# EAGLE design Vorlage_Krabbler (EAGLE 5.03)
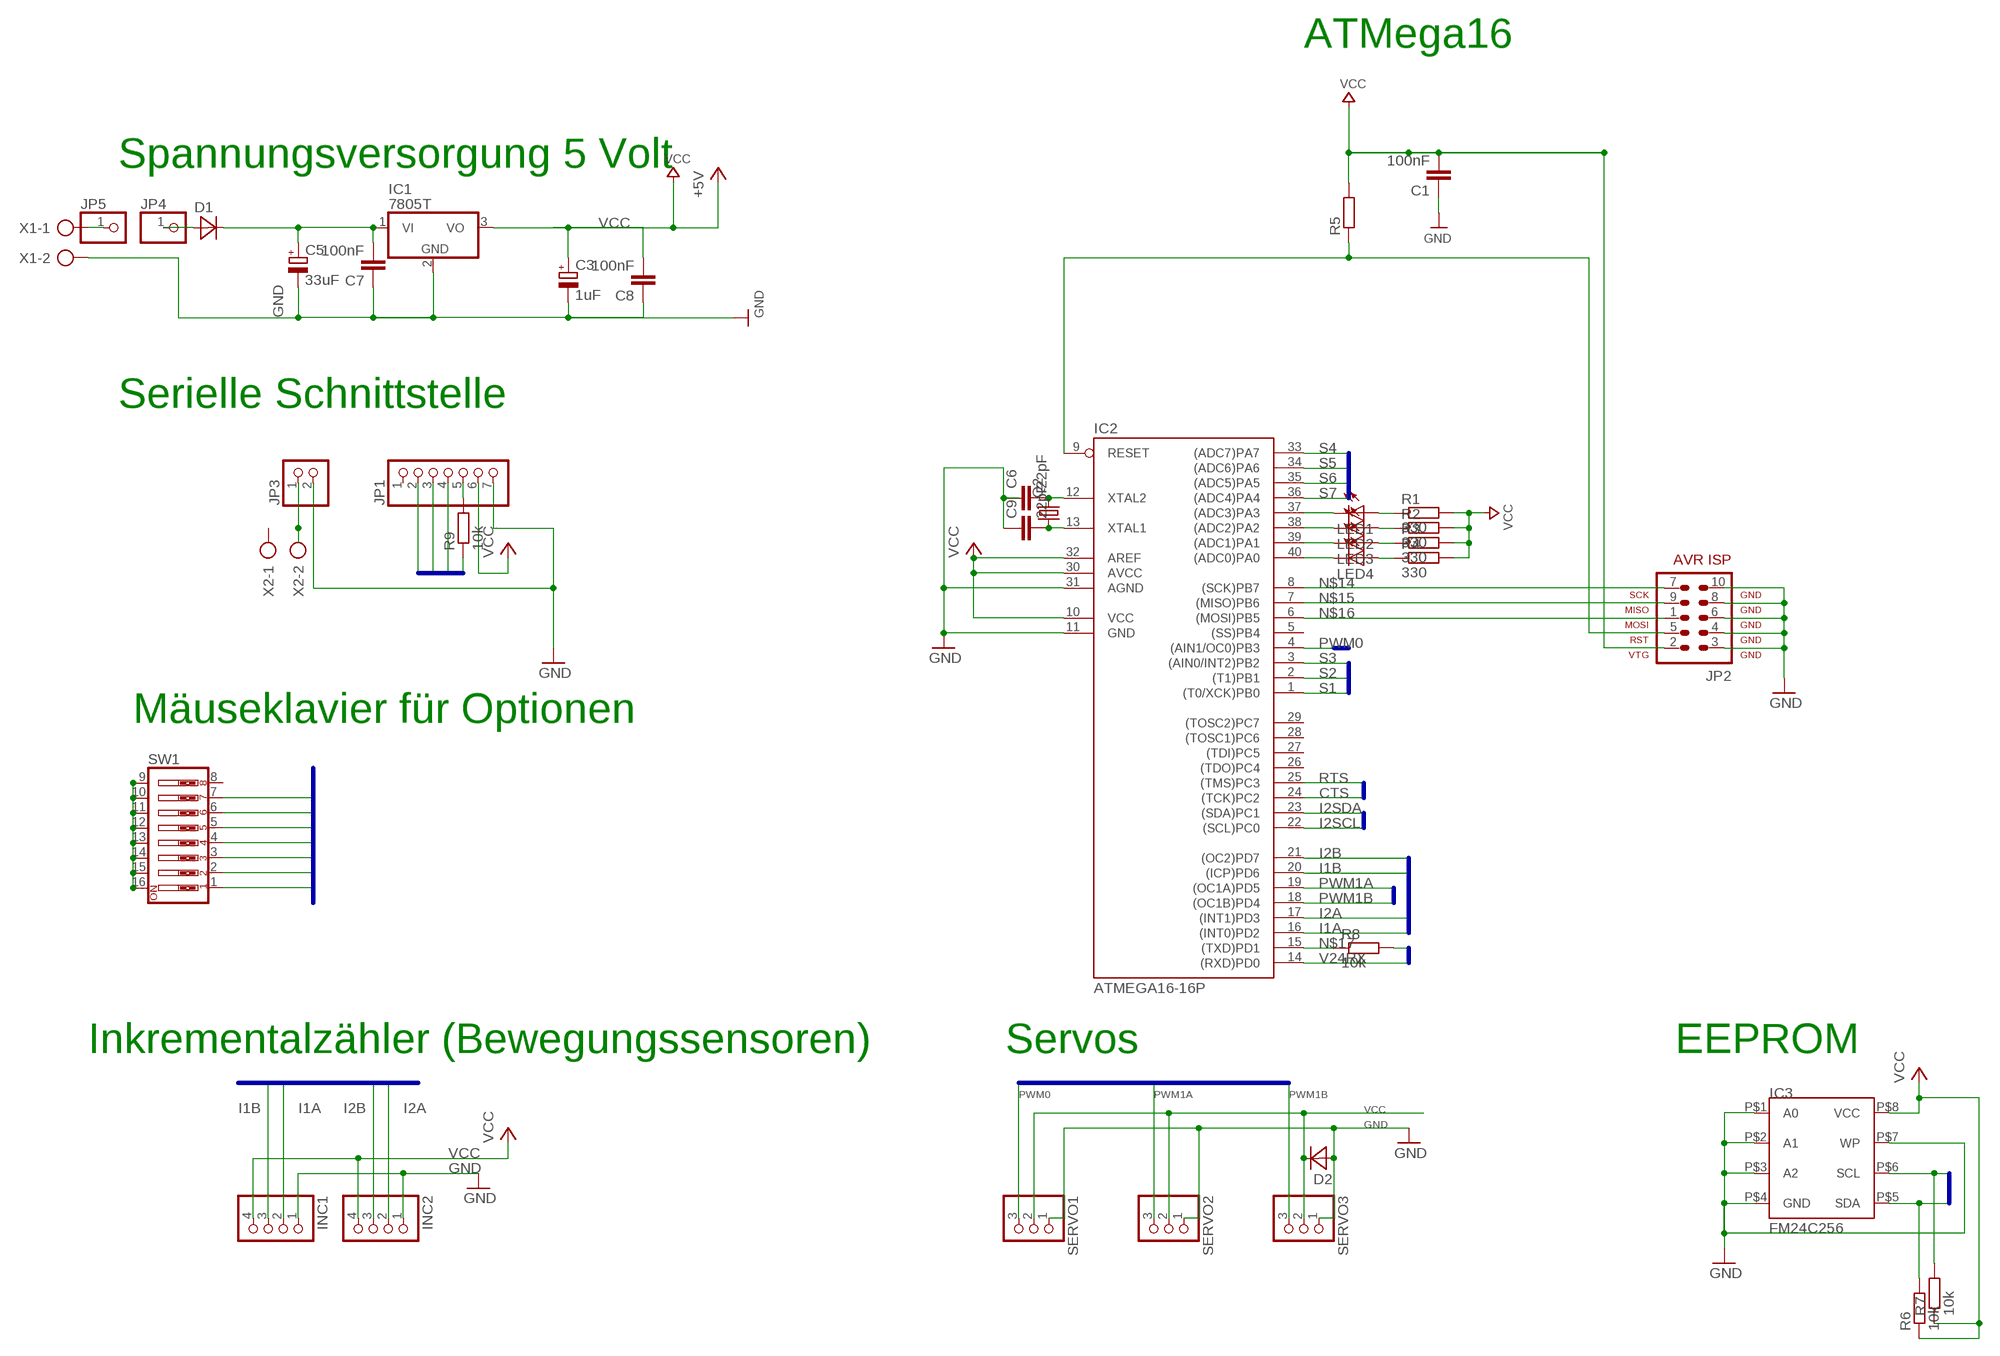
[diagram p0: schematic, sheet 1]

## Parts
C1  100nF  C-EUC0805  [C0805]
C3  1uF  CPOL-EUE2.5-5  [E2,5-5]
C5  33uF  CPOL-EUE2.5-5  [E2,5-5]
C6  22pF  C-EUC0805  [C0805]
C7  100nF  C-EUC0805  [C0805]
C8  100nF  C-EUC0805  [C0805]
C9  22pF  C-EUC0805  [C0805]
D1  DIODE-10  [D-10]
D2  DIODE-10  [D-10]
IC1  7805T  [TO220H]
IC2  ATMEGA16-16P  [DIL40]
IC3  FM24C256  [EIAJ-SOIC-8]
INC1  PINHD-1X4  [1X04]
INC2  PINHD-1X4  [1X04]
JP1  PINHD-1X7  [1X07]
JP2  AVR-ISP-10  [AVR-ISP-10]
JP3  PINHD-1X2  [1X02]
JP4  PINHD-1X1  [1X01]
JP5  PINHD-1X1  [1X01]
LED1  LED5MM  [LED5MM]
LED2  LED5MM  [LED5MM]
LED3  LED5MM  [LED5MM]
LED4  LED5MM  [LED5MM]
Q2  CRYTALHC49S  [HC49/S]
R1  330  R-EU_M1206  [M1206]
R2  330  R-EU_M1206  [M1206]
R3  330  R-EU_M1206  [M1206]
R4  330  R-EU_M1206  [M1206]
R5  R-EU_M1206  [M1206]
R6  10k  R-EU_M1206  [M1206]
R7  10k  R-EU_M1206  [M1206]
R8  10k  R-EU_M1206  [M1206]
R9  10k  R-EU_M1206  [M1206]
SERVO1  PINHD-1X3  [1X03]
SERVO2  PINHD-1X3  [1X03]
SERVO3  PINHD-1X3  [1X03]
SW1  SW_DIP-8  [EDG-08]
X1  AK500/2  [AK500/2]
X2  AK500/2  [AK500/2]

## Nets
/RESET: IC2.9(RESET) JP2.5 R5.1
CTS: IC2.24((TCK)PC2) JP1.2
GND: C1.1 C3.- C5.- C6.1 C7.1 C8.1 C9.1 D2.1(A) IC1.2(GND) IC2.11(GND) IC2.31(AGND) IC3.P$1(A0) IC3.P$2(A1) IC3.P$3(A2) IC3.P$4(GND) IC3.P$7(WP) INC1.1 INC2.1 JP1.7 JP2.3 JP2.4 JP2.6 JP2.8 JP2.10 JP3.2 SERVO1.1 SERVO2.1 SERVO3.1 SW1.9 SW1.10 SW1.11 SW1.12 SW1.13 SW1.14 SW1.15 SW1.16 X1.2
I1A: IC2.16((INT0)PD2) INC1.2
I1B: IC2.20((ICP)PD6) INC1.3
I2A: IC2.17((INT1)PD3) INC2.2
I2B: IC2.21((OC2)PD7) INC2.3
I2SCL: IC2.22((SCL)PC0) IC3.P$6(SCL) R7.2
I2SDA: IC2.23((SDA)PC1) IC3.P$5(SDA) R6.2
N$1: LED1.A R1.1
N$2: LED2.A R2.1
N$3: C6.2 IC2.12(XTAL2) Q2.2
N$4: C9.2 IC2.13(XTAL1) Q2.1
N$5: IC2.37((ADC3)PA3) LED1.K(C)
N$6: LED3.A R3.1
N$7: LED4.A R4.1
N$8: IC2.38((ADC2)PA2) LED2.K(C)
N$9: D1.1(A) JP4.1
N$10: IC2.39((ADC1)PA1) LED3.K(C)
N$11: IC2.40((ADC0)PA0) LED4.K(C)
N$12: C5.+ C7.2 D1.2(K) IC1.1(VI)
N$13: JP5.1 X1.1
N$14: IC2.8((SCK)PB7) JP2.7
N$15: IC2.7((MISO)PB6) JP2.9
N$16: IC2.6((MOSI)PB5) JP2.1
N$17: IC2.15((TXD)PD1) R8.1
N$18: JP3.1 X2.2
N$19: JP1.5 R9.2
PWM0: IC2.4((AIN1/OC0)PB3) SERVO1.3
PWM1A: IC2.19((OC1A)PD5) SERVO2.3
PWM1B: IC2.18((OC1B)PD4) SERVO3.3
RTS: IC2.25((TMS)PC3) R9.1
S1: IC2.1((T0/XCK)PB0) SW1.1
S2: IC2.2((T1)PB1) SW1.2
S3: IC2.3((AIN0/INT2)PB2) SW1.3
S4: IC2.33((ADC7)PA7) SW1.4
S5: IC2.34((ADC6)PA6) SW1.5
S6: IC2.35((ADC5)PA5) SW1.6
S7: IC2.36((ADC4)PA4) SW1.7
V24RX: IC2.14((RXD)PD0) JP1.3
V24TX: JP1.4 R8.2
VCC: C1.2 C3.+ C8.2 D2.2(K) IC1.3(VO) IC2.10(VCC) IC2.30(AVCC) IC2.32(AREF) IC3.P$8(VCC) INC1.4 INC2.4 JP1.6 JP2.2 R1.2 R2.2 R3.2 R4.2 R5.2 R6.1 R7.1 SERVO1.2 SERVO2.2 SERVO3.2 ; supply symbol labelled +5V
Unconnected: IC2.5((SS)PB4) IC2.26((TDO)PC4) IC2.27((TDI)PC5) IC2.28((TOSC1)PC6) IC2.29((TOSC2)PC7) JP1.1 SW1.8 X2.1

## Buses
PWM0,PWM1A,PWM1B
V24RX,V24TX,RTS,CTS
I1A,I1B,I2A,I2B
I2SCL,I2SDA
S1,S2,S3,S4,S5,S6,S7

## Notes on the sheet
- ATMega16
- Spannungsversorgung 5 Volt
- Serielle Schnittstelle
- Mäuseklavier für Optionen
- Servos | EEPROM
- Inkrementalzähler (Bewegungssensoren)

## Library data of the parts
C1 C6-C9 = rcl:C-EU: CAPACITOR, European symbol
C3 C5 = rcl:CPOL-EU: POLARIZED CAPACITOR, European symbol
D1 D2 = discrete:DIODE-10
IC1 = linear:78*: Positive VOLTAGE REGULATOR
IC2 = avr:ATMEGA16*P: MICROCONTROLLER 16 Kbytes FLASH 1 kbytes SRAM 512 bytes EEPROM USART 8-channel 10 bit ADC
IC3 = ramtron:FM24C256
INC1 INC2 = pinhead:PINHD-1X4: PIN HEADER
JP1 = pinhead:PINHD-1X7: PIN HEADER
JP2 = atmel_3:AVR-ISP-10: AVR ISP-10 Serial Programming Header
JP3 = pinhead:PINHD-1X2: PIN HEADER
JP4 JP5 = pinhead:PINHD-1X1: PIN HEADER
LED1-LED4 = LED:LED: LED
Q2 = crystal:CRYTAL: CRYSTAL
R1-R9 = rcl:R-EU_: RESISTOR, European symbol
SERVO1-SERVO3 = pinhead:PINHD-1X3: PIN HEADER
SW1 = special:SW_DIP-8: DIP SWITCH
X1 X2 = con-ptr500:AK500/2: CONNECTOR

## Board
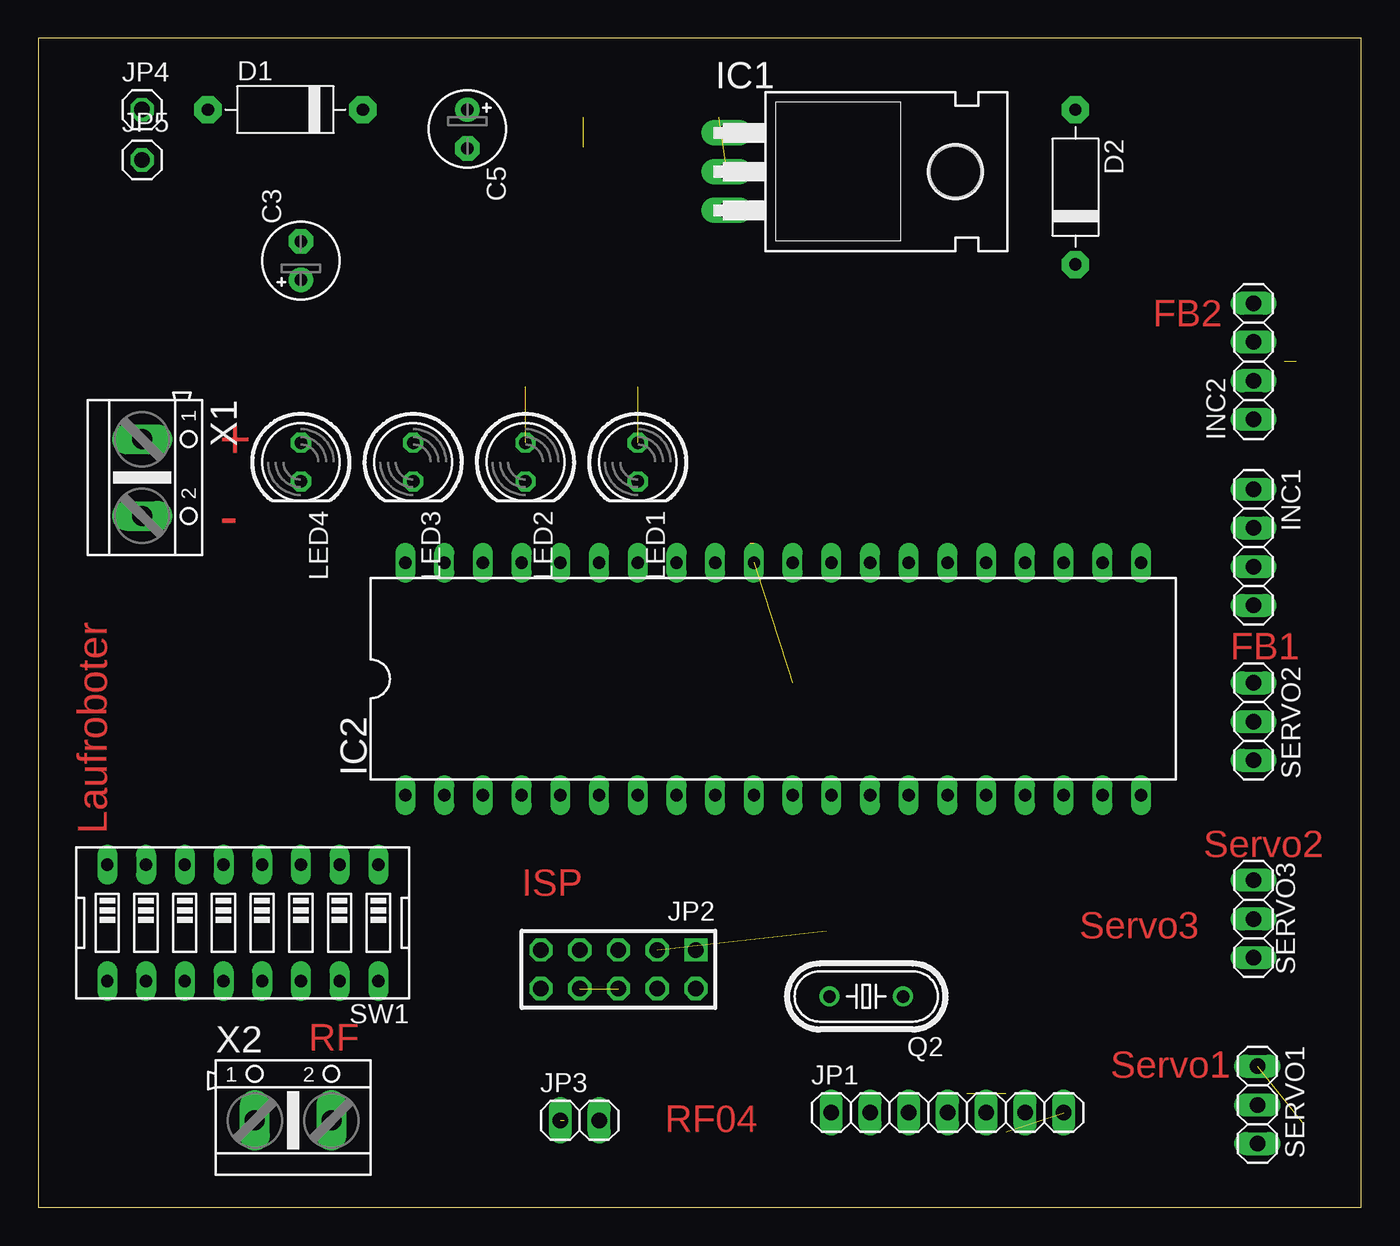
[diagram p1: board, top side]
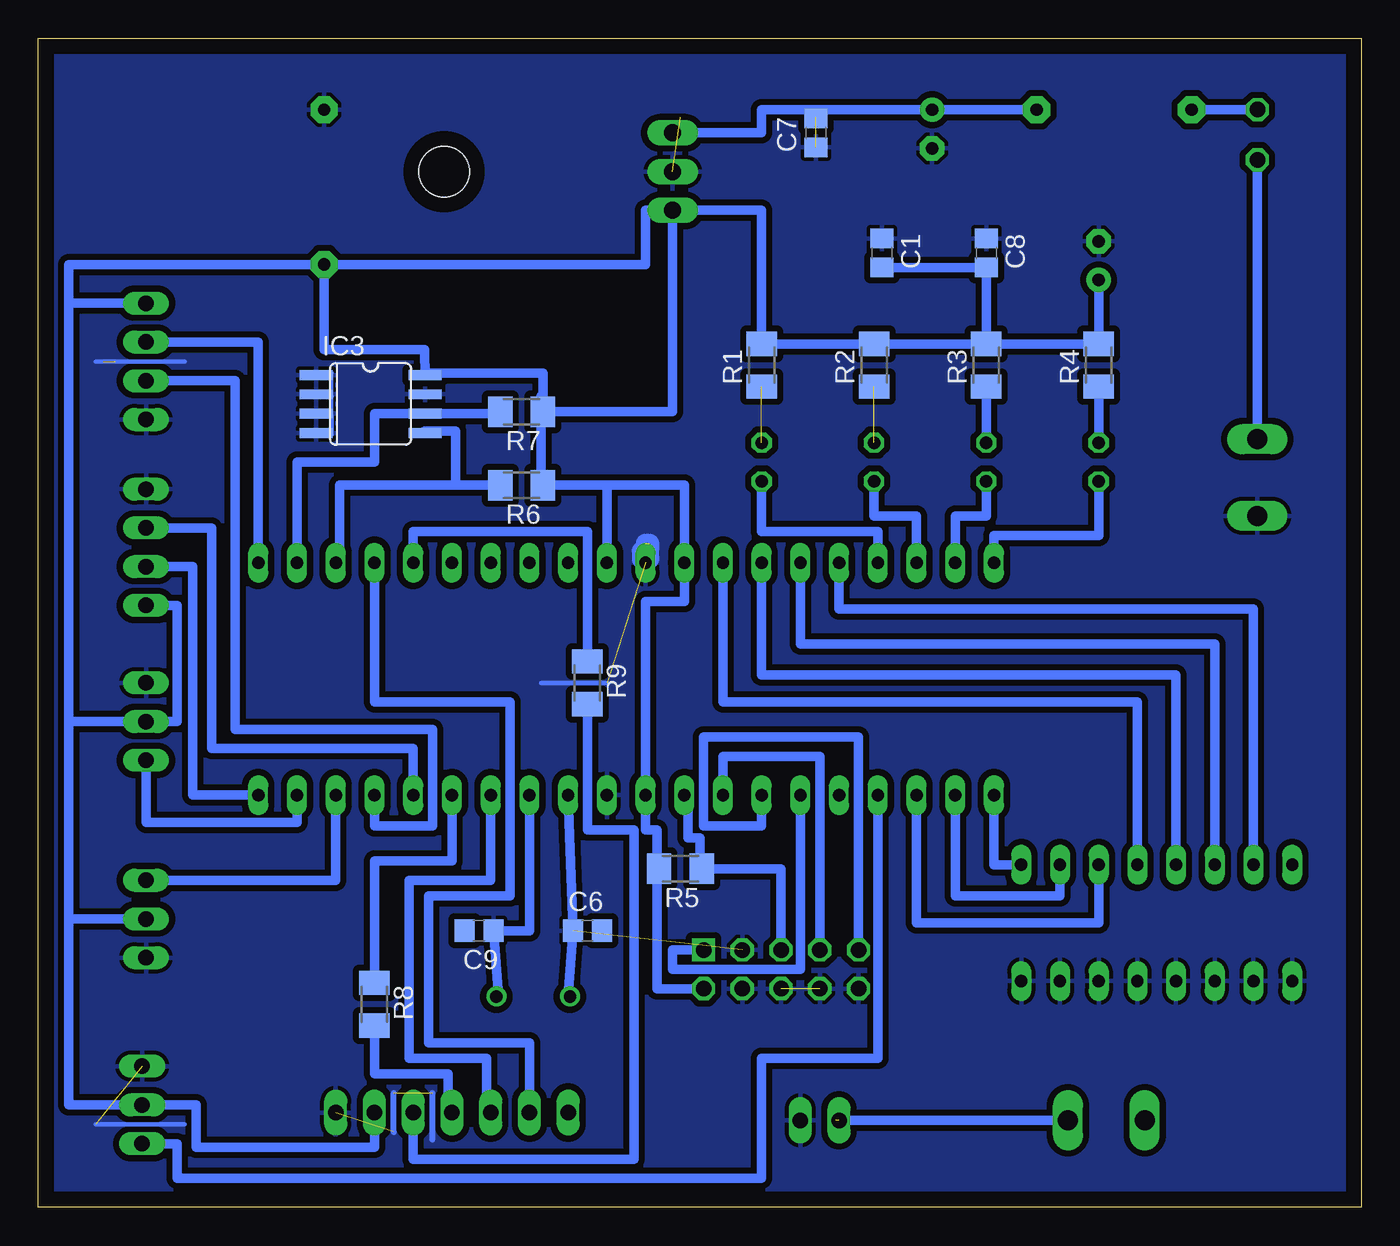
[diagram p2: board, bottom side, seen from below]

Size 86.79 x 76.7 mm. Coordinates in mm from the lower left corner, seen from the top.
Outline: 0,0 86.79,0 86.79,76.7 0,76.7 0,0
Copper layers (1*16): Top 0.035mm / dielectric 1.5mm / Bottom 0.035mm
Design rules "default": minimum track width 10mil, minimum drill 24mil, track to track 16mil, track to pad 16mil, pad to pad 16mil, via to via 16mil, smd to smd 16mil, copper to edge 40mil, drill to drill 16mil, minimum pad ring 10mil, minimum via ring 8mil, stop-mask expansion 4mil, vias tented up to drill 0mil, thermal gap 10mil

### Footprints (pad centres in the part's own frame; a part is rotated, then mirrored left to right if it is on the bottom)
C0805 = smd 1.3 x 1.5: 1 -0.95,0; 2 0.95,0
E2,5-5 = drill 0.813 pad 1.6 round: + -1.27,0 | drill 0.813 pad 1.6 octagon: - 1.27,0
D-10 = drill 0.813 pad 1.778 octagon: 1 -5.08,0; 2 5.08,0
TO220H = drill 1.118 long: 1 -2.54,-10.16; 2 0,-10.16; 3 2.54,-10.16 | hole 3.302: 0,4.826
DIL40 = drill 0.813 long: 1 -24.13,-7.62; 2 -21.59,-7.62; 3 -19.05,-7.62; 4 -16.51,-7.62; 5 -13.97,-7.62; 6 -11.43,-7.62; 7 -8.89,-7.62; 8 -6.35,-7.62; 9 -3.81,-7.62; 10 -1.27,-7.62; 11 1.27,-7.62; 12 3.81,-7.62; 13 6.35,-7.62; 14 8.89,-7.62; 15 11.43,-7.62; 16 13.97,-7.62; 17 16.51,-7.62; 18 19.05,-7.62; 19 21.59,-7.62; 20 24.13,-7.62; 21 24.13,7.62; 22 21.59,7.62; 23 19.05,7.62; 24 16.51,7.62; 25 13.97,7.62; 26 11.43,7.62; 27 8.89,7.62; 28 6.35,7.62; 29 3.81,7.62; 30 1.27,7.62; 31 -1.27,7.62; 32 -3.81,7.62; 33 -6.35,7.62; 34 -8.89,7.62; 35 -11.43,7.62; 36 -13.97,7.62; 37 -16.51,7.62; 38 -19.05,7.62; 39 -21.59,7.62; 40 -24.13,7.62
EIAJ-SOIC-8 = smd 0.65 x 2.15: P$1 -1.905,-3.576; P$2 -0.635,-3.576; P$3 0.635,-3.576; P$4 1.905,-3.576; P$5 1.905,3.576; P$6 0.635,3.576; P$7 -0.635,3.576; P$8 -1.905,3.576
1X04 = drill 1.016 long: 1 -3.81,0; 2 -1.27,0; 3 1.27,0; 4 3.81,0
1X07 = drill 1.016 long: 1 -7.62,0; 2 -5.08,0; 3 -2.54,0; 4 0,0; 5 2.54,0; 6 5.08,0; 7 7.62,0
AVR-ISP-10 = drill 1.016 square: 1 -5.08,-1.27 | drill 1.016 octagon: 2 -5.08,1.27; 3 -2.54,-1.27; 4 -2.54,1.27; 5 0,-1.27; 6 0,1.27; 7 2.54,-1.27; 8 2.54,1.27; 9 5.08,-1.27; 10 5.08,1.27
1X02 = drill 1.016 long: 1 -1.27,0; 2 1.27,0
1X01 = drill 1.016 octagon: 1 0,0
LED5MM = drill 0.813 octagon: A -1.27,0; K 1.27,0
HC49/S = drill 0.813 round: 1 -2.413,0; 2 2.413,0
M1206 = smd 1.6 x 2: 1 -1.4,0; 2 1.4,0
1X03 = drill 1.016 long: 1 -2.54,0; 2 0,0; 3 2.54,0
EDG-08 = drill 0.813 long: 1 -8.89,-3.81; 2 -6.35,-3.81; 3 -3.81,-3.81; 4 -1.27,-3.81; 5 1.27,-3.81; 6 3.81,-3.81; 7 6.35,-3.81; 8 8.89,-3.81; 9 8.89,3.81; 10 6.35,3.81; 11 3.81,3.81; 12 1.27,3.81; 13 -1.27,3.81; 14 -3.81,3.81; 15 -6.35,3.81; 16 -8.89,3.81
AK500/2 = drill 1.321 long: 1 -2.515,0; 2 2.515,0

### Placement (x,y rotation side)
C1  31.46,62.61 270 bottom
C3  17.23,62.1 90 top
C5  28.16,70.73 270 top
C6  50.76,18.16 0 bottom
C7  35.78,70.48 90 bottom
C8  24.6,62.61 270 bottom
C9  57.87,18.16 180 bottom
D1  16.22,72 0 top
D2  68.03,66.92 270 top
IC1  55.33,67.94 270 top
IC2  48.22,34.67 0 top
IC3  64.99,52.7 270 bottom
INC1  79.72,43.3 270 top
INC2  79.72,55.49 90 top
JP1  59.65,6.22 0 top
JP2  38.06,15.62 180 top
JP3  35.52,5.71 0 top
JP4  6.82,72 0 top
JP5  6.82,68.7 0 top
LED1  39.33,48.89 270 top
LED2  31.97,48.89 270 top
LED3  24.6,48.89 270 top
LED4  17.23,48.89 270 top
Q2  54.32,13.84 180 top
R1  39.33,55.24 90 bottom
R2  31.97,55.24 90 bottom
R3  24.6,55.24 90 bottom
R4  17.23,55.24 90 bottom
R5  44.67,22.22 180 bottom
R6  55.08,47.37 180 bottom
R7  55.08,52.19 180 bottom
R8  64.73,13.33 270 bottom
R9  50.76,34.41 270 bottom
SERVO1  79.97,6.73 270 top
SERVO2  79.72,31.87 270 top
SERVO3  79.72,18.92 90 top
SW1  13.42,18.66 180 top
X1  6.82,47.87 270 top
X2  16.73,5.71 0 top

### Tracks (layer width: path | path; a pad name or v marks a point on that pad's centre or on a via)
/RESET
  Bottom 0.61: JP2.5 38.06,22.22 R5.1 43.4,22.22 43.4,24.25 44.16,24.25 44.16,27.05 IC2.9
CTS
  Bottom 0.61: JP1.2 54.57,10.79 61.18,10.79 61.18,20.44 55.84,20.44 55.84,33.14 64.73,33.14 64.73,33.4 IC2.24
GND  (10 unrouted)
  Bottom 0.254: 67.53,51.94 67.53,50.67 IC3.P$4 | IC3.P$7 61.43,53.21 | IC3.P$1 67.53,54.73 67.53,53.21 | 67.53,51.94 67.53,53.21 | IC3.P$3 67.53,51.94 | 67.53,53.21 IC3.P$2
  Bottom 0.305: 77.18,55.49 81.75,55.49 82.51,55.49 83.02,55.49 | 77.18,5.46 83.02,5.46 | 49.49,34.41 53.81,34.41
  Bottom 0.406: 60.92,4.44 60.92,7.49 | 63.46,4.95 63.46,7.49
  Bottom 1.27: IC2.31 46.95,43.56 | 46.7,43.56 46.7,42.54 47.21,42.54 47.21,43.05
  pour Bottom: 4.79,76.07 86.07,76.32 86.07,0.88 0.47,0.63 0.47,76.07
I1A
  Bottom 0.61: IC2.16 62.19,30.09 75.4,30.09 75.4,44.57 INC1.2
I1B
  Bottom 0.61: INC1.3 76.67,42.03 76.67,27.05 IC2.20
I2A
  Bottom 0.61: IC2.17 64.73,25.01 60.92,25.01 60.92,31.36 73.88,31.36 73.88,54.22 INC2.2
I2B
  Bottom 0.61: IC2.21 72.35,56.76 INC2.3
I2SCL
  Bottom 0.61: IC2.22 69.81,48.89 64.73,48.89 64.73,52.07 IC3.P$6 56.35,52.07 56.35,52.19 | 56.35,52.45 56.35,52.19 | 56.35,52.19 R7.2
I2SDA
  Bottom 0.254: 61.43,50.92 IC3.P$5
  Bottom 0.61: R6.2 59.4,47.37 | 59.4,47.37 59.4,50.92 61.43,50.92 61.43,50.8 IC3.P$5 | IC2.23 67.02,42.29 67.02,47.37 59.4,47.37
N$1  (1 unrouted)
N$2  (1 unrouted)
N$3
  Bottom 0.61: IC2.12 51.71,18.16 52.03,13.84 Q2.2
N$4
  Bottom 0.61: Q2.1 56.6,13.84 56.92,18.16 54.57,18.16 IC2.13
N$5
  Bottom 0.61: IC2.37 31.71,44.32 39.33,44.32 LED1.K
N$6
  Bottom 0.61: 24.6,53.97 R3.1 LED3.A
N$7
  Bottom 0.61: LED4.A R4.1
N$8
  Bottom 0.61: IC2.38 29.17,45.33 31.97,45.33 LED2.K
N$9
  Bottom 0.61: JP4.1 D1.1
N$10
  Bottom 0.61: IC2.39 26.63,45.33 24.6,45.33 LED3.K
N$11
  Bottom 0.61: LED4.K 17.23,44.06 24.09,44.06 IC2.40
N$12
  Bottom 0.61: D1.2 C5.+ 35.78,72 | 35.78,71.24 C7.2 35.78,72 | 35.78,72 39.33,72 39.33,70.48 IC1.1
N$13
  Bottom 0.61: X1.1 JP5.1
N$14
  Bottom 0.61: IC2.8 41.87,29.59 35.52,29.59 JP2.7 35.52,16.63
N$15
  Bottom 0.61: JP2.9 32.98,30.86 43.14,30.86 43.14,25.01 39.33,25.01 IC2.7
N$16
  Bottom 0.61: JP2.1 45.17,16.89 45.17,15.62 36.79,15.62 IC2.6
N$17
  Bottom 0.61: IC2.15 59.65,22.73 64.73,22.73 R8.1 64.73,14.6
N$18  (1 unrouted)
  Bottom 0.61: X2.2 JP3.1
N$19
  Bottom 0.61: JP1.5 62.19,3.17 47.71,3.17 47.71,24.76 50.76,24.76 R9.2
PWM0
  Bottom 0.61: SERVO1.3 77.69,4.19 77.69,1.9 39.33,1.9 39.33,9.77 31.71,9.77 IC2.4
PWM1A
  Bottom 0.61: SERVO2.3 79.72,25.27 69.81,25.27 IC2.19
PWM1B
  Bottom 0.61: SERVO3.3 67.27,21.46 IC2.18
RTS
  Bottom 0.61: IC2.25 62.19,44.32 50.76,44.32 R9.1 50.76,35.68
  Bottom 0.813: R9.1 50.89,35.81 51.02,35.94 50.76,36.19
S1
  Bottom 0.61: SW1.1 24.09,22.47 IC2.1
S2
  Bottom 0.61: IC2.2 26.63,20.44 19.77,20.44 SW1.2
S3
  Bottom 0.61: IC2.3 29.17,18.66 17.23,18.66 SW1.3
S4
  Bottom 0.61: IC2.33 41.87,33.14 14.69,33.14 SW1.4
  Bottom 0.813: SW1.4 14.69,22.22
S5
  Bottom 0.61: IC2.34 39.33,34.92 12.15,34.92 SW1.5
S6
  Bottom 0.61: IC2.35 36.79,36.95 9.61,36.95 SW1.6
S7
  Bottom 0.61: SW1.7 7.07,39.24 34.25,39.24 IC2.36
V24RX
  Bottom 0.61: JP1.3 57.37,6.22 57.37,9.77 62.45,9.77 62.45,21.46 57.11,21.46 IC2.14
V24TX
  Bottom 0.61: JP1.4 59.91,6.22 59.91,8.76 64.73,8.76 R8.2
VCC
  Bottom 0.61: 53.56,47.37 49.49,47.37 | R7.1 53.68,54.73 61.41,54.73 | 49.49,47.37 IC2.30 | 49.49,47.37 44.41,47.37 IC2.32 44.41,39.75 46.95,39.75 IC2.10 46.95,24.76 46.19,24.76 46.19,22.22 R5.2 | C1.2 C8.2 R3.2 | IC1.3 46.95,65.4 46.95,61.84 D2.2 | 84.8,59.3 INC2.4 | 84.8,31.87 SERVO2.2 77.69,31.87 77.69,39.49 INC1.4 | 84.8,18.92 SERVO3.2 | 84.8,18.92 84.8,6.73 83.78,6.73 | 84.8,59.3 84.8,61.84 D2.2 | 84.8,18.92 84.8,31.87 | 84.8,31.87 84.8,59.3 | 46.19,21.97 46.19,14.35 JP2.2 | JP1.6 64.73,3.93 76.42,3.93 76.42,6.73 83.78,6.73 | 83.78,6.73 SERVO1.2 | IC3.P$8 61.43,56.13 61.43,56.26 68.03,56.26 D2.2 | R7.1 53.81,53.21 53.81,47.37 R6.1 | R7.1 45.17,52.19 IC1.3 | C3.+ R4.2 R3.2 | R3.2 24.85,56.64 24.85,56.51 | R2.2 R3.2 | R2.2 31.97,56.51 | R2.2 R1.2 39.33,65.4 IC1.3 | R3.2 24.6,56.51
  Bottom 0.813: R5.2 45.94,22.22 46.19,21.97 | R6.1 53.56,47.37 | IC2.32 44.67,42.29 arc90 44.41,42.03

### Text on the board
Top: FB2 | + | - | FB1 | Servo2 | Laufroboter | ISP | Servo3 | RF | Servo1 | RF04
